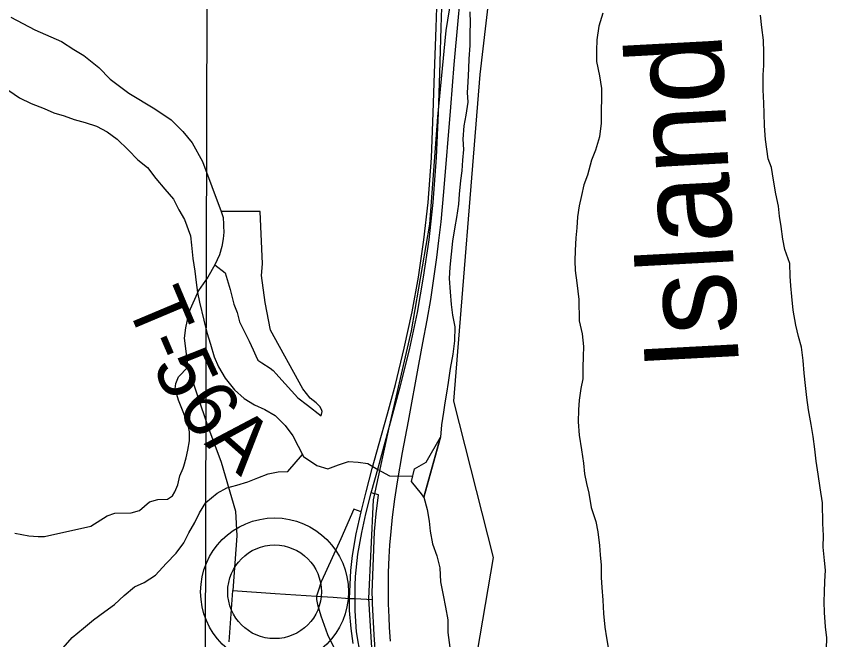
# Model space of a CAD drawing. Extents: x 2.1 to 8.9, y 14.1 to 20.9.
# Drawn here: x 7.249 to 8.065, y 16.441 to 17.069 of the extents above; entities that cross this region are included whole.
import ezdxf

# ---------------------------------------------------------------- set-up
doc = ezdxf.new("R2010")
doc.units = 0
for name, color, linetype in [('Default', 7, 'Continuous'), ('GM_X_City_Street', 7, 'Continuous'), ('GM_X_Interchange_Ramps', 7, 'Continuous'), ('GM_X_Minor_River_Text', 7, 'Continuous'), ('GM_X_Rail_Line_Text', 7, 'Continuous'), ('GM_X_State_Location', 7, 'Continuous'), ('GM_X_State_Route', 7, 'Continuous'), ('GM_X_State_Shield', 7, 'Continuous'), ('GM_X_Township_Text', 7, 'Continuous'), ('GM_X_Unincorporated', 7, 'Continuous'), ('GM_X_Unincorporated_Location', 7, 'Continuous'), ('SC_Shading1', 7, 'Continuous'), ('SH_Cut_Line', 7, 'Continuous'), ('TX_P_Misc', 7, 'Continuous')]:
    doc.layers.add(name, color=color, linetype=linetype)

msp = doc.modelspace()

# ---------------------------------------------------------------- linework, layer by layer
at = {"layer": 'Default'}
for p, q in [((7.7159, 17.01051), (7.73627, 17.18403)), ((7.68935, 16.68153), (7.7159, 17.01051)), ((7.72928, 16.52417), (7.68935, 16.68153)), ((7.71345, 16.42948), (7.72928, 16.52417))]:
    msp.add_line(p, q, dxfattribs=at)
at = {"layer": 'GM_X_City_Street'}
for p, q in [((7.49468, 16.87245), (7.45534, 16.87238)), ((7.49685, 16.81979), (7.49468, 16.87245)), ((7.44891, 16.81879), (7.45933, 16.81068)), ((7.49586, 16.80792), (7.49685, 16.81979)), ((7.45933, 16.81068), (7.46441, 16.79391)), ((7.4995, 16.78094), (7.49586, 16.80792)), ((7.46441, 16.79391), (7.46816, 16.77934)), ((7.46816, 16.77934), (7.47147, 16.77095)), ((7.50483, 16.75291), (7.4995, 16.78094)), ((7.47147, 16.77095), (7.47382, 16.76125)), ((7.47382, 16.76125), (7.48361, 16.74204)), ((7.53737, 16.69395), (7.50483, 16.75291)), ((7.48361, 16.74204), (7.48758, 16.7331)), ((7.48758, 16.7331), (7.49034, 16.72725)), ((7.49034, 16.72725), (7.49231, 16.72283)), ((7.49231, 16.72283), (7.49616, 16.72019)), ((7.49616, 16.72019), (7.50454, 16.71487)), ((7.41244, 16.70612), (7.42181, 16.71576)), ((7.50454, 16.71487), (7.50755, 16.71248)), ((7.50755, 16.71248), (7.51066, 16.70918)), ((7.40952, 16.69944), (7.41244, 16.70612)), ((7.51066, 16.70918), (7.51318, 16.70606)), ((7.51318, 16.70606), (7.53244, 16.68502)), ((7.40889, 16.69401), (7.40952, 16.69944)), ((7.41223, 16.68253), (7.40889, 16.69401)), ((7.54488, 16.68441), (7.53737, 16.69395)), ((7.41787, 16.66896), (7.41223, 16.68253)), ((7.53244, 16.68502), (7.54207, 16.67749)), ((7.54207, 16.67749), (7.55584, 16.66675)), ((7.55097, 16.67994), (7.54488, 16.68441)), ((7.55471, 16.67618), (7.55097, 16.67994)), ((7.5564, 16.67321), (7.55471, 16.67618)), ((7.55584, 16.66675), (7.55685, 16.67101)), ((7.55685, 16.67101), (7.5564, 16.67321)), ((7.42204, 16.65727), (7.41787, 16.66896)), ((7.42351, 16.65059), (7.42204, 16.65727)), ((7.4233, 16.6414), (7.42351, 16.65059)), ((7.42184, 16.63222), (7.4233, 16.6414)), ((7.41996, 16.62428), (7.42184, 16.63222)), ((7.41766, 16.61594), (7.41996, 16.62428)), ((7.41369, 16.60633), (7.41687, 16.61402)), ((7.41687, 16.61402), (7.41766, 16.61594)), ((7.41182, 16.59735), (7.41369, 16.60633)), ((7.40869, 16.59005), (7.41182, 16.59735)), ((7.40618, 16.58608), (7.40869, 16.59005)), ((7.37319, 16.57126), (7.383, 16.58003)), ((7.383, 16.58003), (7.3915, 16.58245)), ((7.3915, 16.58245), (7.40117, 16.58295)), ((7.40117, 16.58295), (7.40618, 16.58608)), ((7.32414, 16.5556), (7.34063, 16.56604)), ((7.34063, 16.56604), (7.34815, 16.56855)), ((7.34815, 16.56855), (7.36484, 16.56896)), ((7.36484, 16.56896), (7.37319, 16.57126)), ((7.27747, 16.54519), (7.32414, 16.5556)), ((7.24764, 16.54851), (7.26174, 16.54598)), ((7.26174, 16.54598), (7.27097, 16.54516)), ((7.27097, 16.54516), (7.27747, 16.54519)), ((7.46349, 16.43902), (7.46695, 16.49097))]:
    msp.add_line(p, q, dxfattribs=at)
at = {"layer": 'GM_X_Interchange_Ramps'}
msp.add_line((7.44097, 17.09977), (7.43801, 16.03935), dxfattribs=at)
at = {"layer": 'GM_X_Rail_Line_Text'}
for p, q in [((7.67155, 17.05764), (7.67301, 17.1024)), ((7.67681, 17.05777), (7.67827, 17.10253)), ((7.67016, 17.01177), (7.67155, 17.05764)), ((7.67575, 17.02287), (7.67681, 17.05777)), ((7.67542, 17.0119), (7.67575, 17.02287)), ((7.66877, 16.97187), (7.67016, 17.01177)), ((7.67403, 16.97201), (7.67542, 17.0119)), ((7.66689, 16.92669), (7.66877, 16.97187)), ((7.67215, 16.92683), (7.67403, 16.97201)), ((7.66349, 16.88159), (7.66689, 16.92669)), ((7.66875, 16.88172), (7.67215, 16.92683)), ((7.65925, 16.84392), (7.66349, 16.88159)), ((7.66451, 16.84405), (7.66875, 16.88172)), ((7.65383, 16.80625), (7.65925, 16.84392)), ((7.65908, 16.80638), (7.66451, 16.84405)), ((7.64746, 16.77156), (7.65383, 16.80625)), ((7.65276, 16.77086), (7.65908, 16.80638)), ((7.63963, 16.73471), (7.64746, 16.77156)), ((7.6447, 16.73319), (7.65276, 16.77086)), ((7.63065, 16.69832), (7.63963, 16.73471)), ((7.63559, 16.69608), (7.6447, 16.73319)), ((7.62272, 16.66888), (7.63065, 16.69832)), ((7.62385, 16.65257), (7.63559, 16.69608)), ((7.61671, 16.64711), (7.62272, 16.66888)), ((7.60737, 16.6137), (7.61671, 16.64711)), ((7.6137, 16.61545), (7.62385, 16.65257)), ((7.6011, 16.59005), (7.60737, 16.6137)), ((7.60643, 16.58905), (7.6137, 16.61545)), ((7.59613, 16.56995), (7.6011, 16.59005)), ((7.60084, 16.56816), (7.60643, 16.58905)), ((7.59113, 16.54792), (7.59613, 16.56995)), ((7.59682, 16.54936), (7.60084, 16.56816)), ((7.58743, 16.52605), (7.59113, 16.54792)), ((7.59289, 16.52729), (7.59682, 16.54936)), ((7.58581, 16.51091), (7.58743, 16.52605)), ((7.59063, 16.50501), (7.59289, 16.52729)), ((7.58497, 16.49697), (7.58581, 16.51091)), ((7.59025, 16.49598), (7.59063, 16.50501)), ((7.58463, 16.48291), (7.58497, 16.49697)), ((7.59015, 16.48267), (7.59025, 16.49598)), ((7.58458, 16.47058), (7.58463, 16.48291)), ((7.5901, 16.47033), (7.59015, 16.48267)), ((7.58612, 16.45244), (7.58458, 16.47058)), ((7.59163, 16.44928), (7.5901, 16.47033)), ((7.588, 16.43741), (7.58612, 16.45244)), ((7.59578, 16.42356), (7.59163, 16.44928))]:
    msp.add_line(p, q, dxfattribs=at)
at = {"layer": 'GM_X_State_Location'}
for p, q in [((7.7057, 17.07363), (7.7059, 17.06261)), ((7.83949, 17.07237), (7.83557, 17.05899)), ((7.99967, 17.05792), (7.99831, 17.07006)), ((7.7059, 17.06261), (7.70572, 17.05197)), ((7.83557, 17.05899), (7.83355, 17.04527)), ((8.00104, 17.04502), (7.99967, 17.05792)), ((7.70572, 17.05197), (7.70556, 17.0398)), ((7.83355, 17.04527), (7.83298, 17.03461)), ((8.00165, 17.03249), (8.00104, 17.04502)), ((7.70556, 17.0398), (7.70468, 17.0261)), ((7.83298, 17.03461), (7.83319, 17.02359)), ((8.00151, 17.01957), (8.00165, 17.03249)), ((7.70468, 17.0261), (7.7041, 17.01658)), ((7.83319, 17.02359), (7.8361, 17.00921)), ((7.7041, 17.01658), (7.70359, 17.00289)), ((8.00093, 17.01005), (8.00151, 17.01957)), ((7.8361, 17.00921), (7.83824, 16.99632)), ((8.00083, 16.99485), (8.00093, 17.01005)), ((7.70359, 17.00289), (7.70303, 16.99224)), ((7.83824, 16.99632), (7.83803, 16.98682)), ((7.70303, 16.99224), (7.70358, 16.98275)), ((8.00145, 16.98156), (8.00083, 16.99485)), ((7.70358, 16.98275), (7.70155, 16.9694)), ((7.83803, 16.98682), (7.83789, 16.97389)), ((8.00201, 16.97168), (8.00145, 16.98156)), ((7.83789, 16.97389), (7.83774, 16.96134)), ((8.00225, 16.95877), (8.00201, 16.97168)), ((7.70155, 16.9694), (7.69948, 16.95872)), ((7.69948, 16.95872), (7.69859, 16.9454)), ((7.83774, 16.96134), (7.8361, 16.94763)), ((8.00326, 16.9451), (8.00225, 16.95877)), ((7.8361, 16.94763), (7.83218, 16.93425)), ((7.69859, 16.9454), (7.69916, 16.93477)), ((8.0059, 16.92539), (8.00326, 16.9451)), ((7.69916, 16.93477), (7.69822, 16.92411)), ((7.83218, 16.93425), (7.82819, 16.92429)), ((7.69822, 16.92411), (7.69766, 16.91346)), ((7.82819, 16.92429), (7.82393, 16.90901)), ((8.00909, 16.91671), (8.0059, 16.92539)), ((8.01122, 16.90421), (8.00909, 16.91671)), ((7.69766, 16.91346), (7.69633, 16.90355)), ((7.82393, 16.90901), (7.82032, 16.89944)), ((7.69633, 16.90355), (7.69469, 16.88983)), ((7.82032, 16.89944), (7.81786, 16.88875)), ((8.01375, 16.89019), (8.01122, 16.90421)), ((7.69469, 16.88983), (7.69411, 16.87994)), ((8.01626, 16.8777), (8.01375, 16.89019)), ((7.81786, 16.88875), (7.81579, 16.87807)), ((7.69411, 16.87994), (7.69208, 16.8666)), ((7.81579, 16.87807), (7.8141, 16.86702)), ((8.01719, 16.86784), (8.01626, 16.8777)), ((7.69208, 16.8666), (7.69037, 16.85707)), ((7.8141, 16.86702), (7.81316, 16.85598)), ((8.01891, 16.85723), (8.01719, 16.86784)), ((7.69037, 16.85707), (7.68798, 16.84258)), ((8.02065, 16.84472), (8.01891, 16.85723)), ((7.81316, 16.85598), (7.81221, 16.84608)), ((7.68798, 16.84258), (7.68671, 16.82963)), ((7.81221, 16.84608), (7.81169, 16.83315)), ((8.02275, 16.83412), (8.02065, 16.84472)), ((7.81169, 16.83315), (7.81112, 16.82288)), ((8.02755, 16.82015), (8.02275, 16.83412)), ((7.68671, 16.82963), (7.68544, 16.81631)), ((7.68544, 16.81631), (7.68489, 16.8049)), ((7.81112, 16.82288), (7.81169, 16.81301)), ((8.02817, 16.80724), (8.02755, 16.82015)), ((7.81169, 16.81301), (7.81343, 16.8005)), ((7.68489, 16.8049), (7.68589, 16.79162)), ((7.81343, 16.8005), (7.81526, 16.78382)), ((8.02872, 16.79775), (8.02817, 16.80724)), ((8.02969, 16.78675), (8.02872, 16.79775)), ((7.68589, 16.79162), (7.68689, 16.77871)), ((7.81526, 16.78382), (7.81565, 16.76254)), ((8.03108, 16.7731), (8.02969, 16.78675)), ((7.68689, 16.77871), (7.68822, 16.7681)), ((7.68822, 16.7681), (7.69034, 16.75636)), ((8.03363, 16.75795), (8.03108, 16.7731)), ((7.81565, 16.76254), (7.81855, 16.7493)), ((7.69034, 16.75636), (7.69022, 16.7423)), ((8.0365, 16.7466), (8.03363, 16.75795)), ((7.81855, 16.7493), (7.81993, 16.7364)), ((8.03934, 16.73602), (8.0365, 16.7466)), ((7.69022, 16.7423), (7.68857, 16.72897)), ((7.81993, 16.7364), (7.81973, 16.72652)), ((8.04111, 16.72237), (8.03934, 16.73602)), ((7.68857, 16.72897), (7.68581, 16.71448)), ((7.81973, 16.72652), (7.81918, 16.71549)), ((8.0421, 16.70985), (8.04111, 16.72237)), ((7.68581, 16.71448), (7.6838, 16.70038)), ((7.81918, 16.71549), (7.81939, 16.7041)), ((7.81939, 16.7041), (7.8173, 16.69418)), ((8.04347, 16.69734), (8.0421, 16.70985)), ((7.6838, 16.70038), (7.6821, 16.68971)), ((7.8173, 16.69418), (7.81562, 16.68237)), ((8.04484, 16.68521), (8.04347, 16.69734)), ((7.6821, 16.68971), (7.68039, 16.6798)), ((7.68039, 16.6798), (7.67905, 16.67027)), ((7.81562, 16.68237), (7.81505, 16.67286)), ((8.04658, 16.67271), (8.04484, 16.68521)), ((7.67905, 16.67027), (7.67701, 16.6577)), ((7.81505, 16.67286), (7.81451, 16.66069)), ((8.04913, 16.65794), (8.04658, 16.67271)), ((7.67701, 16.6577), (7.67611, 16.64514)), ((7.81451, 16.66069), (7.81552, 16.64741)), ((8.05125, 16.64582), (8.04913, 16.65794)), ((7.67611, 16.64514), (7.65943, 16.5848)), ((7.81552, 16.64741), (7.81807, 16.63264)), ((8.053, 16.63332), (8.05125, 16.64582)), ((7.81807, 16.63264), (7.81984, 16.619)), ((8.05437, 16.62119), (8.053, 16.63332)), ((8.05613, 16.60792), (8.05437, 16.62119)), ((7.81984, 16.619), (7.82117, 16.60839)), ((7.82117, 16.60839), (7.82287, 16.59854)), ((8.05828, 16.59429), (8.05613, 16.60792)), ((7.82287, 16.59854), (7.82533, 16.58871)), ((7.82533, 16.58871), (7.82787, 16.57433)), ((8.06046, 16.57914), (8.05828, 16.59429)), ((7.65943, 16.5848), (7.66269, 16.57232)), ((7.66269, 16.57232), (7.6648, 16.56059)), ((7.82787, 16.57433), (7.8323, 16.56036)), ((8.06085, 16.55825), (8.06046, 16.57914)), ((7.6648, 16.56059), (7.66575, 16.55073)), ((7.8323, 16.56036), (7.8344, 16.54976)), ((8.06145, 16.54611), (8.06085, 16.55825)), ((7.66575, 16.55073), (7.66788, 16.53786)), ((7.8344, 16.54976), (7.83617, 16.53612)), ((8.0613, 16.53433), (8.06145, 16.54611)), ((7.66788, 16.53786), (7.67228, 16.52578)), ((7.83617, 16.53612), (7.83672, 16.52663)), ((8.06268, 16.52106), (8.0613, 16.53433)), ((7.67228, 16.52578), (7.67554, 16.51369)), ((7.83672, 16.52663), (7.83767, 16.51639)), ((7.83767, 16.51639), (7.83791, 16.50387)), ((8.06362, 16.5112), (8.06268, 16.52106)), ((7.67554, 16.51369), (7.67618, 16.49965)), ((8.06308, 16.4998), (8.06362, 16.5112)), ((7.67618, 16.49965), (7.67871, 16.48603)), ((7.83791, 16.50387), (7.83847, 16.494)), ((8.06252, 16.48953), (8.06308, 16.4998)), ((7.83847, 16.494), (7.83947, 16.48111)), ((7.67871, 16.48603), (7.68121, 16.47392)), ((8.06233, 16.47927), (8.06252, 16.48953)), ((7.68121, 16.47392), (7.68333, 16.46143)), ((7.83947, 16.48111), (7.8401, 16.46783)), ((8.06253, 16.46864), (8.06233, 16.47927)), ((7.8401, 16.46783), (7.8415, 16.4538)), ((8.06356, 16.45423), (8.06253, 16.46864)), ((7.68333, 16.46143), (7.68358, 16.44852)), ((7.8415, 16.4538), (7.84321, 16.4432)), ((8.0649, 16.44324), (8.06356, 16.45423)), ((7.68358, 16.44852), (7.68538, 16.43336)), ((7.84321, 16.4432), (7.84533, 16.43146)), ((8.06473, 16.43222), (8.0649, 16.44324))]:
    msp.add_line(p, q, dxfattribs=at)
at = {"layer": 'GM_X_State_Route'}
for radius in [0.0744, 0.04716]:
    msp.add_circle((7.50904, 16.4895), radius, dxfattribs=at)
at = {"layer": 'GM_X_State_Shield'}
for p, q in [((7.24343, 17.06825), (7.2676, 17.05534)), ((7.2676, 17.05534), (7.29455, 17.04381)), ((7.29455, 17.04381), (7.30688, 17.03549)), ((7.30688, 17.03549), (7.31721, 17.02958)), ((7.31721, 17.02958), (7.3322, 17.01761)), ((7.3322, 17.01761), (7.34366, 17.00569)), ((7.34366, 17.00569), (7.36228, 16.99169)), ((7.36228, 16.99169), (7.38852, 16.97591)), ((7.38852, 16.97591), (7.40483, 16.96474)), ((7.40483, 16.96474), (7.41671, 16.95321)), ((7.41671, 16.95321), (7.42593, 16.94169)), ((7.42593, 16.94169), (7.43657, 16.92272)), ((7.43657, 16.92272), (7.45534, 16.87238)), ((7.45534, 16.87238), (7.45722, 16.86656)), ((7.45722, 16.86656), (7.45774, 16.85978)), ((7.45774, 16.85978), (7.45777, 16.85771)), ((7.45777, 16.85771), (7.45785, 16.85153)), ((7.45785, 16.85153), (7.45726, 16.84494)), ((7.45726, 16.84494), (7.45607, 16.8373)), ((7.45607, 16.8373), (7.45356, 16.82882)), ((7.45356, 16.82882), (7.44891, 16.81879)), ((7.44891, 16.81879), (7.44185, 16.80625)), ((7.44185, 16.80625), (7.43242, 16.79299)), ((7.43242, 16.79299), (7.42262, 16.77101)), ((7.42262, 16.77101), (7.41928, 16.75536)), ((7.41928, 16.75536), (7.41803, 16.7451)), ((7.41803, 16.7451), (7.42181, 16.71576)), ((7.42181, 16.71576), (7.44161, 16.65714)), ((7.44161, 16.65714), (7.45541, 16.62013)), ((7.45541, 16.62013), (7.46967, 16.57088)), ((7.46967, 16.57088), (7.47105, 16.54603)), ((7.47105, 16.54603), (7.46695, 16.49097)), ((7.46695, 16.49097), (7.50977, 16.48792)), ((7.50977, 16.48792), (7.55136, 16.48527)), ((7.55136, 16.48527), (7.56801, 16.48402)), ((7.56801, 16.48402), (7.58463, 16.48291)), ((7.58463, 16.48291), (7.59015, 16.48267)), ((7.59015, 16.48267), (7.60763, 16.48184))]:
    msp.add_line(p, q, dxfattribs=at)
at = {"layer": 'GM_X_Township_Text'}
msp.add_line((7.50904, 16.4895), (7.50904, 16.4895), dxfattribs=at)
at = {"layer": 'GM_X_Unincorporated'}
for p, q in [((7.6137, 16.58731), (7.60643, 16.58905)), ((7.61144, 16.56819), (7.6137, 16.58731)), ((7.58888, 16.5727), (7.5757, 16.54279)), ((7.59613, 16.56995), (7.58888, 16.5727)), ((7.60953, 16.55009), (7.61144, 16.56819)), ((7.6083, 16.51466), (7.60953, 16.55009)), ((7.5757, 16.54279), (7.56002, 16.50828)), ((7.60741, 16.48876), (7.6083, 16.51466)), ((7.56002, 16.50828), (7.55585, 16.49945)), ((7.55585, 16.49945), (7.55316, 16.49122)), ((7.55316, 16.49122), (7.55136, 16.48527)), ((7.55136, 16.48527), (7.55135, 16.48171)), ((7.55135, 16.48171), (7.55209, 16.47666)), ((7.60763, 16.48184), (7.60741, 16.48876)), ((7.60763, 16.47782), (7.60763, 16.48184)), ((7.55209, 16.47666), (7.55557, 16.46526)), ((7.60942, 16.44612), (7.60763, 16.47782)), ((7.55557, 16.46526), (7.56217, 16.44663)), ((7.56217, 16.44663), (7.5694, 16.4321)), ((7.61134, 16.41883), (7.60942, 16.44612))]:
    msp.add_line(p, q, dxfattribs=at)
at = {"layer": 'SC_Shading1'}
for p, q in [((7.69464, 17.13967), (7.68152, 17.0547)), ((7.6937, 17.06447), (7.69564, 17.08261)), ((7.68985, 17.02037), (7.6937, 17.06447)), ((7.68152, 17.0547), (7.67301, 16.9679)), ((7.68638, 16.97751), (7.68985, 17.02037)), ((7.67952, 16.89214), (7.68638, 16.97751)), ((7.67301, 16.9679), (7.66489, 16.8598)), ((7.67665, 16.86207), (7.67952, 16.89214)), ((7.66489, 16.8598), (7.64651, 16.75227)), ((7.67446, 16.84318), (7.67665, 16.86207)), ((7.67229, 16.82615), (7.67446, 16.84318)), ((7.66982, 16.80725), (7.67229, 16.82615)), ((7.66626, 16.7839), (7.66982, 16.80725)), ((7.6625, 16.76312), (7.66626, 16.7839)), ((7.65844, 16.74026), (7.6625, 16.76312)), ((7.64651, 16.75227), (7.62454, 16.6562)), ((7.65428, 16.7183), (7.65844, 16.74026)), ((7.6438, 16.66131), (7.65428, 16.7183)), ((7.63776, 16.62965), (7.6438, 16.66131)), ((7.62454, 16.6562), (7.60826, 16.58208)), ((7.63281, 16.60016), (7.63776, 16.62965)), ((7.63014, 16.58275), (7.63281, 16.60016)), ((7.60826, 16.58208), (7.60372, 16.48266)), ((7.62787, 16.56464), (7.63014, 16.58275)), ((7.62638, 16.55039), (7.62787, 16.56464)), ((7.625, 16.53664), (7.62638, 16.55039)), ((7.6243, 16.52427), (7.625, 16.53664)), ((7.62371, 16.50903), (7.6243, 16.52427)), ((7.62361, 16.49201), (7.62371, 16.50903)), ((7.62371, 16.47737), (7.62361, 16.49201)), ((7.60372, 16.48266), (7.60847, 16.40252)), ((7.6243, 16.46401), (7.62371, 16.47737)), ((7.6247, 16.45372), (7.6243, 16.46401)), ((7.62569, 16.43987), (7.6247, 16.45372))]:
    msp.add_line(p, q, dxfattribs=at)
at = {"layer": 'SH_Cut_Line'}
for p, q in [((7.7159, 17.01051), (7.73627, 17.18403)), ((7.68935, 16.68153), (7.7159, 17.01051)), ((7.72928, 16.52417), (7.68935, 16.68153)), ((7.71345, 16.42948), (7.72928, 16.52417))]:
    msp.add_line(p, q, dxfattribs=at)
at = {"layer": 'TX_P_Misc'}
for p, q in [((7.2414, 16.99429), (7.25224, 16.98696)), ((7.25224, 16.98696), (7.26417, 16.98118)), ((7.26417, 16.98118), (7.27722, 16.9762)), ((7.27722, 16.9762), (7.28683, 16.97189)), ((7.28683, 16.97189), (7.29718, 16.96874)), ((7.29718, 16.96874), (7.30715, 16.9652)), ((7.30715, 16.9652), (7.31826, 16.96207)), ((7.31826, 16.96207), (7.32975, 16.95857)), ((7.32975, 16.95857), (7.34055, 16.95276)), ((7.34055, 16.95276), (7.35062, 16.94542)), ((7.35062, 16.94542), (7.36154, 16.93466)), ((7.36154, 16.93466), (7.37131, 16.92464)), ((7.37131, 16.92464), (7.38101, 16.9169)), ((7.38101, 16.9169), (7.38967, 16.9057)), ((7.38967, 16.9057), (7.3987, 16.89489)), ((7.3987, 16.89489), (7.40733, 16.88484)), ((7.40733, 16.88484), (7.41255, 16.87431)), ((7.41255, 16.87431), (7.4185, 16.86456)), ((7.4185, 16.86456), (7.42426, 16.84795)), ((7.42426, 16.84795), (7.42528, 16.83846)), ((7.42528, 16.83846), (7.42677, 16.82516)), ((7.42677, 16.82516), (7.42863, 16.81225)), ((7.42863, 16.81225), (7.43007, 16.80086)), ((7.43007, 16.80086), (7.43147, 16.791)), ((7.43147, 16.791), (7.43363, 16.78115)), ((7.43363, 16.78115), (7.43792, 16.76297)), ((7.43792, 16.76297), (7.44091, 16.75048)), ((7.44091, 16.75048), (7.44464, 16.73878)), ((7.44464, 16.73878), (7.44839, 16.7263)), ((7.44839, 16.7263), (7.45246, 16.71613)), ((7.45246, 16.71613), (7.45923, 16.7045)), ((7.45923, 16.7045), (7.46866, 16.69295)), ((7.46866, 16.69295), (7.4784, 16.68407)), ((7.4784, 16.68407), (7.48882, 16.67788)), ((7.48882, 16.67788), (7.49921, 16.67321)), ((7.49921, 16.67321), (7.50963, 16.66701)), ((7.50963, 16.66701), (7.51978, 16.657)), ((7.51978, 16.657), (7.52728, 16.64654)), ((7.52728, 16.64654), (7.53288, 16.63603)), ((7.65943, 16.5848), (7.67611, 16.64514)), ((7.6618, 16.62018), (7.67611, 16.64514)), ((7.53288, 16.63603), (7.53809, 16.62588)), ((7.52254, 16.61061), (7.53716, 16.6277)), ((7.53716, 16.6277), (7.53766, 16.62778)), ((7.53809, 16.62588), (7.55164, 16.61673)), ((7.57328, 16.61732), (7.58345, 16.62064)), ((7.58345, 16.62064), (7.59335, 16.62015)), ((7.55164, 16.61673), (7.56275, 16.61322)), ((7.56275, 16.61322), (7.57328, 16.61732)), ((7.59335, 16.62015), (7.60288, 16.61888)), ((7.60288, 16.61888), (7.61293, 16.61268)), ((7.61293, 16.61268), (7.62489, 16.60615)), ((7.64701, 16.60052), (7.6498, 16.61349)), ((7.6498, 16.61349), (7.6618, 16.62018)), ((7.48215, 16.60037), (7.4923, 16.60445)), ((7.4923, 16.60445), (7.50246, 16.60816)), ((7.50246, 16.60816), (7.51266, 16.61034)), ((7.51266, 16.61034), (7.52254, 16.61061)), ((7.62489, 16.60615), (7.64814, 16.60581)), ((7.46103, 16.59408), (7.47122, 16.59703)), ((7.47122, 16.59703), (7.48215, 16.60037)), ((7.65709, 16.58818), (7.64701, 16.60052)), ((7.43976, 16.57941), (7.45129, 16.58887)), ((7.45129, 16.58887), (7.46103, 16.59408)), ((7.65943, 16.5848), (7.65709, 16.58818)), ((7.43358, 16.56896), (7.43976, 16.57941)), ((7.4289, 16.55931), (7.43358, 16.56896)), ((7.42272, 16.54886), (7.4289, 16.55931)), ((7.41766, 16.53882), (7.42272, 16.54886)), ((7.40996, 16.52833), (7.41766, 16.53882)), ((7.39998, 16.51816), (7.40996, 16.52833)), ((7.38927, 16.50644), (7.39998, 16.51816)), ((7.37769, 16.49889), (7.38927, 16.50644)), ((7.36793, 16.49444), (7.37769, 16.49889)), ((7.35752, 16.48578), (7.36793, 16.49444)), ((7.34788, 16.47676), (7.35752, 16.48578)), ((7.33819, 16.46964), (7.34788, 16.47676)), ((7.32663, 16.46133), (7.33819, 16.46964)), ((7.31659, 16.45307), (7.32663, 16.46133)), ((7.30544, 16.44362), (7.31659, 16.45307)), ((7.29622, 16.43309), (7.30544, 16.44362))]:
    msp.add_line(p, q, dxfattribs=at)

# ---------------------------------------------------------------- texts
at = {"layer": 'GM_X_Minor_River_Text'}
for s, rotation, p in [('T', 292.84239, (7.35904, 16.78024)), ('-', 293.28606, (7.37573, 16.74063)), ('5', 294.83582, (7.38564, 16.71767)), ('6', 309.08887, (7.40849, 16.67284)), ('A', 318.44433, (7.43755, 16.63837))]:
    msp.add_text(s, height=0.05682, rotation=rotation, dxfattribs=at).set_placement(p)
at = {"layer": 'GM_X_Unincorporated_Location'}
msp.add_text('Island', height=0.09484, rotation=93.06639, dxfattribs=at).set_placement((7.97676, 16.71533))

doc.saveas('drawing.dxf')
